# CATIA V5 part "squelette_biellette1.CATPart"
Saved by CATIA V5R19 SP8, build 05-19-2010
Part number: squelette_biellette1
Publications: "Droite.6", "Droite.7", "Plan.3"
Bounding box of the stored display mesh (mm): x 83 to 83, y 246.609 to 319.01, z 21.218 to 59.697
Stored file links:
  G:\EU_thinkMotion\CFAO_2010\MMS_groupe3\MMS_groupe3\A reprendre\amenand\amenand\squelette_biellette1.CATPart
  F:\thinkmotion CFAO v12.1\essuie_glace.CATProduct
  G:\EU_thinkMotion\CFAO_2010\MMS_groupe3\MMS_groupe3\A reprendre\amenand\amenand\squelette_bielle.CATPart
  G:\EU_thinkMotion\CFAO_2010\MMS_groupe3\MMS_groupe3\A reprendre\amenand\amenand\biellette2.CATPart
  G:\EU_thinkMotion\CFAO_2010\MMS_groupe3\MMS_groupe3\A reprendre\amenand\amenand\squelette_biellette2.CATPart
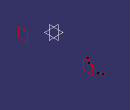
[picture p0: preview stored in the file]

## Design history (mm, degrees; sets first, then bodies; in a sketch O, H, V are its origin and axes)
Set1
  Plane1: linked copy from another document
  Plane2: linked copy from another document
  Point1: linked copy from another document
  Point2: linked copy from another document
Set2 "set géométrique.5"
  Point3: type OnPlane, Support Plane1, H 252.594, V 41.971, Direction (0, 1, 0)
  Point4: type OnPlane, Support Plane1, H 295.525, V 21.218, Direction (0, 1, 0)
  Line1: type PtPt, FirstPoint Point3, SecondPoint Point4
  Line2: type PtPt, FirstPoint Point3, SecondPoint Point1
  Line3: type PtPt, FirstPoint Point4, SecondPoint Point2
Body1 (main body)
